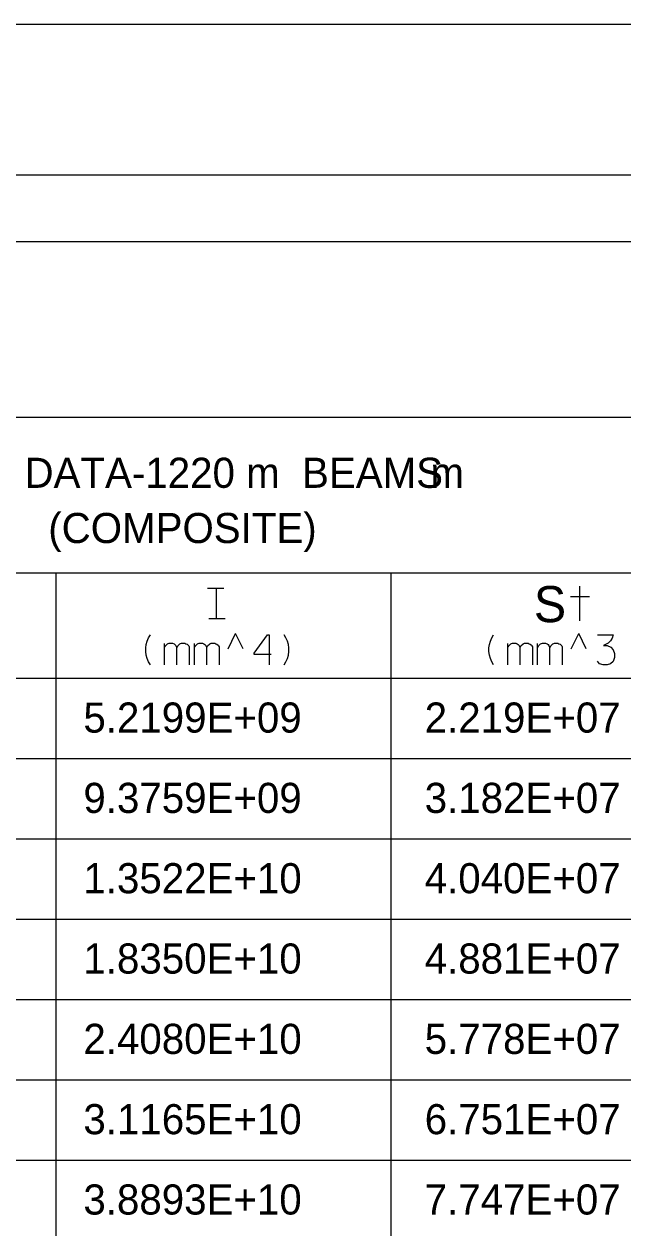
# Model space of a CAD drawing. Extents: x 635698 to 639877, y 296617 to 300175.
# Drawn here: x 636898.4 to 636958.1, y 299944.9 to 300064.8 of the extents above; entities that cross this region are included whole.
import ezdxf

# ---------------------------------------------------------------- set-up
doc = ezdxf.new("R2010")
doc.units = 0
doc.layers.add('2', color=7, linetype='Continuous')
doc.layers.add('PLT-BNDY', color=7, linetype='Continuous')

msp = doc.modelspace()

# ---------------------------------------------------------------- linework, layer by layer
at = {"layer": '2'}
for p, q in [((636545.45, 300049.76), (637331.45, 300049.76)), ((637053.06, 300043.07), (636556.08, 300043.07)), ((637001.69, 300025.57), (636618.31, 300025.57)), ((637001.69, 300010.07), (636819.31, 300010.07)), ((636901.56, 300010.07), (636901.56, 299887.57)), ((636934.94, 300010.07), (636934.94, 299887.57)), ((636916.69, 300008.57), (636918.31, 300008.57)), ((636916.81, 300005.57), (636918.44, 300005.57)), ((636918.72, 300002.55), (636919.47, 300004.05)), ((636920.22, 300002.55), (636919.47, 300004.05)), ((636952.9, 300002.55), (636953.65, 300004.05)), ((636954.4, 300002.55), (636953.65, 300004.05)), ((637001.69, 299999.57), (636819.31, 299999.57)), ((637001.69, 299991.57), (636819.31, 299991.57)), ((637001.69, 299983.57), (636819.31, 299983.57)), ((637001.69, 299975.57), (636819.31, 299975.57)), ((637001.69, 299967.57), (636819.31, 299967.57)), ((637001.69, 299959.57), (636819.31, 299959.57)), ((637001.69, 299951.57), (636819.31, 299951.57))]:
    msp.add_line(p, q, dxfattribs=at)
for points in [[(636917.22, 300008.57), (636917.93, 300008.57)], [(636917.58, 300005.57), (636917.58, 300008.57)], [(636953.76, 300005.32), (636953.76, 300008.77)], [(636954.72, 300007.73), (636952.82, 300007.73)], [(636917.22, 300005.57), (636917.93, 300005.57)], [(636910.99, 300000.94), (636910.8, 300001.25), (636910.66, 300001.58), (636910.57, 300001.91), (636910.52, 300002.26), (636910.52, 300002.62), (636910.57, 300002.97), (636910.66, 300003.3), (636910.8, 300003.63), (636910.99, 300003.94)], [(636923.03, 300001.98), (636921.32, 300001.98), (636921.32, 300002.1), (636922.65, 300003.94), (636922.81, 300003.94), (636922.81, 300000.94)], [(636924.3, 300000.94), (636924.49, 300001.25), (636924.63, 300001.58), (636924.73, 300001.91), (636924.77, 300002.26), (636924.77, 300002.62), (636924.73, 300002.97), (636924.63, 300003.3), (636924.49, 300003.63), (636924.3, 300003.94)], [(636945.18, 300000.94), (636944.99, 300001.25), (636944.85, 300001.58), (636944.75, 300001.91), (636944.71, 300002.26), (636944.71, 300002.62), (636944.75, 300002.97), (636944.85, 300003.3), (636944.99, 300003.63), (636945.18, 300003.94)], [(636955.51, 300003.94), (636957.09, 300003.94), (636957, 300003.59), (636956.83, 300003.33), (636956.6, 300003.09), (636956.12, 300002.86), (636956.48, 300002.86), (636956.86, 300002.69), (636957.09, 300002.45), (636957.21, 300002.08), (636957.21, 300001.67), (636957.09, 300001.27), (636956.83, 300001.04), (636956.48, 300000.94), (636956.08, 300000.94), (636955.72, 300001.04), (636955.51, 300001.3)], [(636912.39, 300002.69), (636912.44, 300002.74), (636912.49, 300002.83), (636912.7, 300003.04), (636912.77, 300003.07), (636912.87, 300003.09), (636913.2, 300003.09), (636913.34, 300003.04), (636913.43, 300002.97), (636913.53, 300002.88), (636913.6, 300002.71), (636913.62, 300002.67), (636913.67, 300002.74), (636913.72, 300002.83), (636913.93, 300003.04), (636914, 300003.07), (636914.07, 300003.09), (636914.43, 300003.09), (636914.52, 300003.04), (636914.64, 300003), (636914.76, 300002.9), (636914.8, 300002.83), (636914.85, 300002.74), (636914.85, 300000.94)], [(636912.39, 300000.94), (636912.39, 300003.07)], [(636913.62, 300000.94), (636913.62, 300002.69)], [(636915.37, 300002.69), (636915.42, 300002.74), (636915.47, 300002.83), (636915.68, 300003.04), (636915.75, 300003.07), (636915.84, 300003.09), (636916.17, 300003.09), (636916.32, 300003.04), (636916.41, 300002.97), (636916.51, 300002.88), (636916.58, 300002.71), (636916.6, 300002.67), (636916.65, 300002.74), (636916.69, 300002.83), (636916.91, 300003.04), (636916.98, 300003.07), (636917.05, 300003.09), (636917.4, 300003.09), (636917.5, 300003.04), (636917.62, 300003), (636917.73, 300002.9), (636917.78, 300002.83), (636917.83, 300002.74), (636917.83, 300000.94)], [(636915.37, 300000.94), (636915.37, 300003.07)], [(636916.6, 300000.94), (636916.6, 300002.69)], [(636946.58, 300002.69), (636946.63, 300002.74), (636946.68, 300002.83), (636946.89, 300003.04), (636946.96, 300003.07), (636947.05, 300003.09), (636947.38, 300003.09), (636947.53, 300003.04), (636947.62, 300002.97), (636947.72, 300002.88), (636947.79, 300002.71), (636947.81, 300002.67), (636947.86, 300002.74), (636947.9, 300002.83), (636948.12, 300003.04), (636948.19, 300003.07), (636948.26, 300003.09), (636948.61, 300003.09), (636948.71, 300003.04), (636948.83, 300003), (636948.94, 300002.9), (636948.99, 300002.83), (636949.04, 300002.74), (636949.04, 300000.94)], [(636946.58, 300000.94), (636946.58, 300003.07)], [(636947.81, 300000.94), (636947.81, 300002.69)], [(636949.56, 300002.69), (636949.6, 300002.74), (636949.65, 300002.83), (636949.86, 300003.04), (636949.94, 300003.07), (636950.03, 300003.09), (636950.36, 300003.09), (636950.5, 300003.04), (636950.6, 300002.97), (636950.69, 300002.88), (636950.76, 300002.71), (636950.79, 300002.67), (636950.83, 300002.74), (636950.88, 300002.83), (636951.09, 300003.04), (636951.16, 300003.07), (636951.23, 300003.09), (636951.59, 300003.09), (636951.68, 300003.04), (636951.8, 300003), (636951.92, 300002.9), (636951.97, 300002.83), (636952.01, 300002.74), (636952.01, 300000.94)], [(636949.56, 300000.94), (636949.56, 300003.07)], [(636950.79, 300000.94), (636950.79, 300002.69)]]:
    msp.add_lwpolyline(points, dxfattribs=at)
at = {"layer": 'PLT-BNDY'}
msp.add_lwpolyline([(636505.45, 300064.76), (637346.45, 300064.76), (637346.45, 299470.76), (636505.45, 299470.76)], close=True, dxfattribs=at)

# ---------------------------------------------------------------- texts
at = {"layer": '2'}
for s, height, p in [('BASIC BEAM DATA-1220 m  BEAMS', 3, (636872.81, 300018.57)), ('m', 3, (636938.88, 300018.57)), ('(COMPOSITE)', 3, (636900.81, 300013.07)), ('S', 3.6, (636949.19, 300005.19)), ('5.2199E+09', 3, (636904.31, 299994.19)), ('2.219E+07', 3, (636938.31, 299994.19)), ('9.3759E+09', 3, (636904.31, 299986.19)), ('3.182E+07', 3, (636938.31, 299986.19)), ('1.3522E+10', 3, (636904.31, 299978.19)), ('4.040E+07', 3, (636938.31, 299978.19)), ('1.8350E+10', 3, (636904.31, 299970.19)), ('4.881E+07', 3, (636938.31, 299970.19)), ('2.4080E+10', 3, (636904.31, 299962.19)), ('5.778E+07', 3, (636938.31, 299962.19)), ('3.1165E+10', 3, (636904.31, 299954.19)), ('6.751E+07', 3, (636938.31, 299954.19)), ('3.8893E+10', 3, (636904.31, 299946.19)), ('7.747E+07', 3, (636938.31, 299946.19))]:
    msp.add_text(s, height=height, dxfattribs=at).set_placement(p)

doc.saveas('drawing.dxf')
